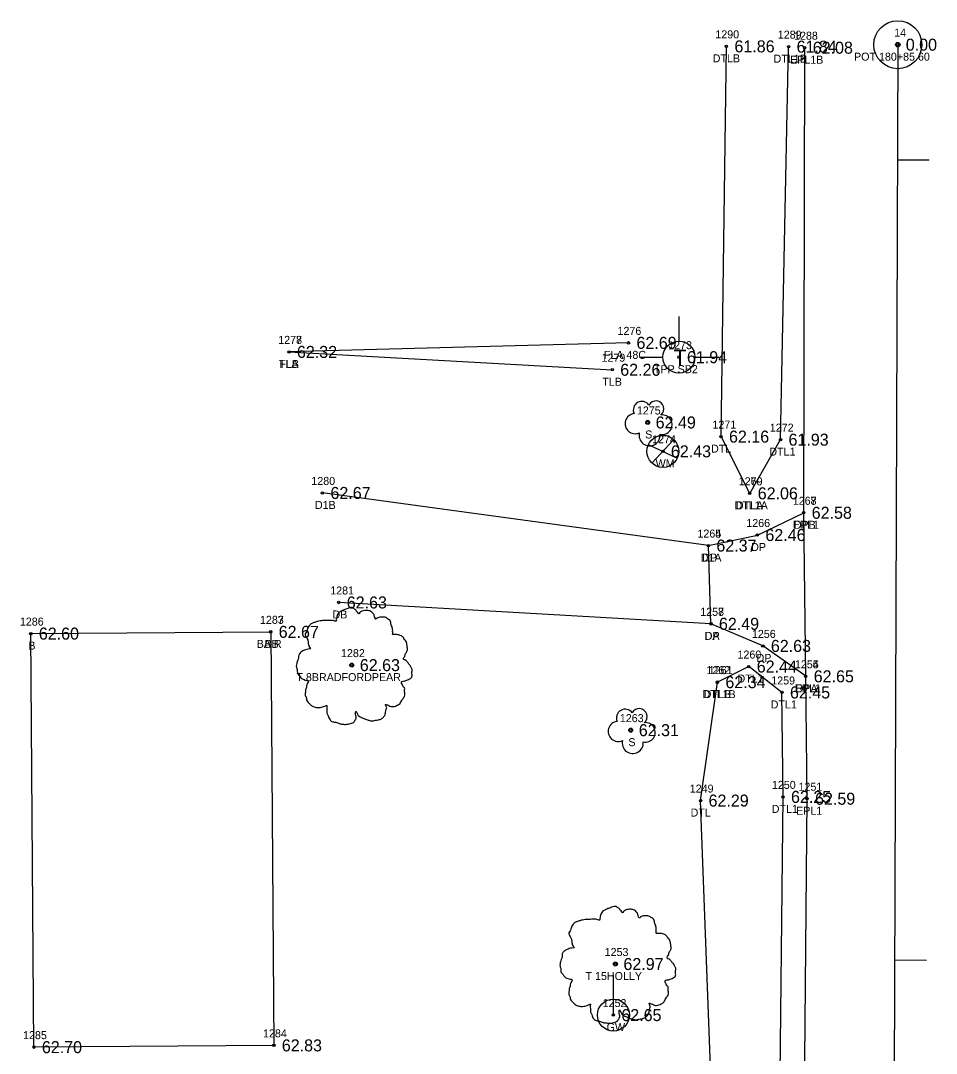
# Model space of a CAD drawing. Extents: x 2420113 to 2422887, y 845323 to 846653.
# Drawn here: x 2420851.4 to 2420965.9, y 846073.7 to 846202.8 of the extents above; entities that cross this region are included whole.
import ezdxf

# ---------------------------------------------------------------- set-up
doc = ezdxf.new("R2010")
doc.units = 0
for name, color, linetype in [('RD_EX_Bldg', 7, 'Continuous'), ('RD_EX_Bldg_txCode', 7, 'Continuous'), ('RD_EX_Driveway', 7, 'Continuous'), ('RD_EX_Driveway_txCode', 7, 'Continuous'), ('RD_EX_Fence_Other', 7, 'Continuous'), ('RD_EX_Fence_Other_txCode', 7, 'Continuous'), ('RD_EX_H2O', 7, 'Continuous'), ('RD_EX_H2O_txCode', 7, 'Continuous'), ('RD_EX_Road', 7, 'Continuous'), ('RD_EX_Road_txCode', 7, 'Continuous'), ('RD_EX_TX_Bldg_ELEV', 7, 'Continuous'), ('RD_EX_TX_Driveway_ELEV', 7, 'Continuous'), ('RD_EX_TX_Fence_Other_ELEV', 7, 'Continuous'), ('RD_EX_TX_H2O_ELEV', 7, 'Continuous'), ('RD_EX_TX_Road_ELEV', 7, 'Continuous'), ('RD_EX_TX_UT_ELEV', 7, 'Continuous'), ('RD_EX_TX_VEG_ELEV', 7, 'Continuous'), ('RD_EX_UT', 7, 'Continuous'), ('RD_EX_UT_txCode', 7, 'Continuous'), ('RD_EX_VEG', 7, 'Continuous'), ('RD_EX_VEG_txCode', 7, 'Continuous'), ('RD_HC_Cl', 7, 'Continuous'), ('RD_HC_Data', 7, 'Continuous'), ('RD_HC_Data_Tic', 7, 'Continuous'), ('RD_HC_Survey_ELEV', 7, 'Continuous'), ('RD_HC_txCode', 7, 'Continuous'), ('RD_SMD_Locator', 7, 'Continuous')]:
    doc.layers.add(name, color=color, linetype=linetype)

msp = doc.modelspace()

# ---------------------------------------------------------------- linework, layer by layer
at = {"layer": 'RD_EX_Bldg'}
msp.add_lwpolyline([(2420882.64, 846126.42), (2420883.03, 846074.73), (2420853.03, 846074.51), (2420852.65, 846126.2), (2420882.64, 846126.42)], dxfattribs=at)
at = {"layer": 'RD_EX_Driveway'}
for p, q in [((2420937.36, 846137.2), (2420889.11, 846143.78)), ((2420937.68, 846127.42), (2420891.15, 846130.09))]:
    msp.add_line(p, q, dxfattribs=at)
msp.add_lwpolyline([(2420949.53, 846120.86), (2420944.17, 846124.66), (2420937.68, 846127.42), (2420937.36, 846137.2), (2420943.49, 846138.52), (2420949.28, 846141.3)], dxfattribs=at)
at = {"layer": 'RD_EX_Fence_Other'}
msp.add_line((2420927.37, 846162.54), (2420884.92, 846161.41), dxfattribs=at)
at = {"layer": 'RD_EX_H2O'}
for points in [[(2420942.53, 846143.73), (2420938.94, 846150.82), (2420939.62, 846199.6)], [(2420942.53, 846143.73), (2420946.38, 846150.44), (2420947.39, 846199.56)], [(2420940.5, 845999.01), (2420945.76, 846017.04), (2420946.69, 846105.79), (2420946.56, 846118.84), (2420942.41, 846122.08), (2420938.49, 846120.13)], [(2420940.5, 845999.01), (2420939.71, 846016.55), (2420936.38, 846105.33), (2420938.49, 846120.13)]]:
    msp.add_lwpolyline(points, dxfattribs=at)
at = {"layer": 'RD_EX_Road'}
msp.add_lwpolyline([(2420911.08, 845716.87), (2420926.22, 845723.04), (2420936.01, 845731.06), (2420942.67, 845742.11), (2420946.54, 845756.04), (2420945.56, 845775.49), (2420946.2, 845794.55), (2420948.14, 845835.31), (2420948.56, 845856.76), (2420948.65, 845897.5), (2420947.59, 845964.03), (2420948.31, 845983.28), (2420948.75, 845998.25), (2420949.7, 846105.56), (2420949.53, 846120.86), (2420949.28, 846141.3), (2420949.41, 846199.43)], dxfattribs=at)
at = {"layer": 'RD_EX_UT'}
for p, q in [((2420933.68, 846165.82), (2420933.68, 846162.75)), ((2420928.75, 846160.76), (2420931.68, 846160.76)), ((2420935.68, 846160.76), (2420938.75, 846160.76)), ((2420930.31, 846147.52), (2420932.98, 846150.42)), ((2420929.83, 846149.82), (2420933.46, 846148.11)), ((2420925.48, 846078.52), (2420925.48, 846083.52))]:
    msp.add_line(p, q, dxfattribs=at)
for centre in [(2420933.68, 846160.75), (2420931.67, 846148.98), (2420925.48, 846078.52)]:
    msp.add_circle(centre, 2, dxfattribs=at)
at = {"layer": 'RD_EX_VEG'}
msp.add_line((2420884.92, 846161.41), (2420925.34, 846159.18), dxfattribs=at)
for centre, radius in [((2420929.77, 846152.59), 0.25), ((2420892.78, 846122.26), 0.25), ((2420892.77, 846122.24), 0.0001), ((2420927.66, 846114.13), 0.25), ((2420925.74, 846084.9), 0.25), ((2420925.73, 846084.88), 0.0001)]:
    msp.add_circle(centre, radius, dxfattribs=at)
for centre, radius, start, end in [((2420929.05, 846154.14), 1.08, 34.9763, 204.756), ((2420930.81, 846154.29), 0.995, 308.7626, 152.0467), ((2420928.2, 846152.44), 1.26, 96.4518, 294.734), ((2420931.61, 846152.31), 1.22, 256.5667, 98.1046), ((2420930.01, 846150.99), 1.32, 166.8827, 5.7589), ((2420926.94, 846115.67), 1.08, 34.9763, 204.756), ((2420928.7, 846115.83), 0.995, 308.7626, 152.0467), ((2420926.09, 846113.97), 1.26, 96.4518, 294.734), ((2420929.5, 846113.85), 1.22, 256.5667, 98.1046), ((2420927.9, 846112.53), 1.32, 166.8827, 5.7589)]:
    msp.add_arc(centre, radius, start, end, dxfattribs=at)
for points in [[(2420892.91, 846129.42), (2420892.61, 846129.45), (2420892.29, 846129.35), (2420892.04, 846129.25), (2420891.81, 846129.17), (2420891.59, 846129.07), (2420891.29, 846128.9), (2420891.06, 846128.7), (2420890.94, 846128.45), (2420890.89, 846128.22), (2420890.84, 846127.95), (2420890.84, 846127.78), (2420890.71, 846127.75), (2420890.56, 846127.78), (2420890.31, 846127.85), (2420890.06, 846127.85), (2420889.81, 846127.85), (2420889.46, 846127.83), (2420889.11, 846127.83), (2420888.84, 846127.78), (2420888.51, 846127.73), (2420888.14, 846127.6), (2420887.79, 846127.48), (2420887.49, 846127.23), (2420887.24, 846126.75), (2420887.11, 846126.4), (2420886.96, 846126.15), (2420887.11, 846125.7), (2420887.29, 846125.35), (2420887.31, 846125.15), (2420887.39, 846124.73), (2420887.49, 846124.5), (2420887.61, 846124.3), (2420887.54, 846124.28), (2420887.16, 846124.23), (2420886.86, 846124.13), (2420886.44, 846123.9), (2420886.22, 846123.68), (2420886.12, 846123.35), (2420886.09, 846123), (2420885.99, 846122.8), (2420885.92, 846122.53), (2420885.89, 846122.45), (2420885.84, 846122.13), (2420885.94, 846121.68), (2420885.97, 846121.33), (2420886.09, 846121.1), (2420886.24, 846120.93), (2420886.42, 846120.68), (2420886.81, 846120.45), (2420887.14, 846120.35), (2420887.34, 846120.33), (2420887.16, 846119.83), (2420887.11, 846119.48), (2420886.99, 846119.08), (2420886.99, 846119), (2420886.94, 846118.53), (2420887.09, 846118.2), (2420887.16, 846117.83), (2420887.34, 846117.6), (2420887.61, 846117.3), (2420887.94, 846117.08), (2420888.44, 846116.95), (2420888.84, 846116.98), (2420889.41, 846117.15), (2420889.66, 846117.23), (2420889.64, 846117.05), (2420889.66, 846116.68), (2420889.66, 846116.26), (2420889.81, 846115.93), (2420889.91, 846115.66), (2420890.06, 846115.41), (2420890.39, 846115.18), (2420890.79, 846115.11), (2420891.21, 846114.96), (2420891.66, 846114.88), (2420892.16, 846114.86), (2420892.76, 846115.01), (2420893.04, 846115.13), (2420893.14, 846115.31), (2420893.34, 846115.68), (2420893.29, 846115.91), (2420893.31, 846116.51), (2420893.41, 846116.33), (2420893.59, 846115.98), (2420894.09, 846115.68), (2420894.49, 846115.51), (2420894.96, 846115.36), (2420895.26, 846115.28), (2420895.74, 846115.36), (2420896.11, 846115.43), (2420896.49, 846115.56), (2420896.79, 846115.83), (2420896.96, 846116.11), (2420897.01, 846116.38), (2420897.09, 846116.75), (2420897.14, 846116.93)], [(2420897.14, 846116.93), (2420897.06, 846117.1), (2420897.01, 846117.35), (2420897.09, 846117.33), (2420897.26, 846117.28), (2420897.54, 846117.15), (2420897.76, 846117.08), (2420898.09, 846117.1), (2420898.36, 846117.2), (2420898.81, 846117.48), (2420899.08, 846117.95), (2420899.36, 846118.35), (2420899.43, 846118.68), (2420899.38, 846118.9), (2420899.36, 846119.4), (2420899.16, 846119.65), (2420899.11, 846119.78), (2420899.01, 846120.18), (2420899.08, 846120.23), (2420899.36, 846120.28), (2420899.73, 846120.4), (2420900.01, 846120.53), (2420900.23, 846120.7), (2420900.31, 846120.93), (2420900.28, 846121.33), (2420900.33, 846121.73), (2420900.26, 846121.88), (2420900.16, 846122.03), (2420900.08, 846122.23), (2420899.93, 846122.38), (2420899.83, 846122.53), (2420899.73, 846122.63), (2420899.61, 846122.78), (2420899.43, 846122.9), (2420899.28, 846122.95), (2420899.23, 846123.1), (2420899.38, 846123.3), (2420899.43, 846123.4), (2420899.46, 846123.63), (2420899.68, 846123.98), (2420899.73, 846124.38), (2420899.68, 846124.8), (2420899.63, 846125.08), (2420899.48, 846125.35), (2420899.28, 846125.6), (2420899.16, 846125.78), (2420898.98, 846125.9), (2420898.66, 846126.03), (2420898.41, 846126.08), (2420898.06, 846126.08), (2420897.86, 846126.13), (2420897.89, 846126.18), (2420897.89, 846126.33), (2420897.89, 846126.6), (2420897.81, 846127.05), (2420897.66, 846127.55), (2420897.66, 846127.58), (2420897.56, 846127.83), (2420897.34, 846128.02), (2420897.16, 846128.12), (2420896.96, 846128.25), (2420896.71, 846128.27), (2420896.41, 846128.27), (2420896.14, 846128.22), (2420895.94, 846128.12), (2420895.76, 846128), (2420895.69, 846128.15), (2420895.59, 846128.45), (2420895.54, 846128.6), (2420895.39, 846128.77), (2420895.16, 846128.97), (2420894.71, 846129.1), (2420894.09, 846129.02), (2420893.79, 846128.82), (2420893.64, 846128.65), (2420893.59, 846128.77), (2420893.39, 846128.97), (2420893.29, 846129.15), (2420893.11, 846129.27), (2420892.96, 846129.37), (2420892.86, 846129.42)], [(2420925.87, 846092.07), (2420925.57, 846092.09), (2420925.25, 846091.99), (2420925, 846091.89), (2420924.77, 846091.82), (2420924.55, 846091.72), (2420924.25, 846091.55), (2420924.02, 846091.35), (2420923.9, 846091.1), (2420923.85, 846090.87), (2420923.8, 846090.6), (2420923.8, 846090.42), (2420923.67, 846090.4), (2420923.52, 846090.42), (2420923.27, 846090.5), (2420923.02, 846090.5), (2420922.77, 846090.5), (2420922.42, 846090.47), (2420922.07, 846090.47), (2420921.8, 846090.42), (2420921.47, 846090.37), (2420921.1, 846090.25), (2420920.75, 846090.12), (2420920.45, 846089.87), (2420920.2, 846089.4), (2420920.07, 846089.05), (2420919.92, 846088.8), (2420920.07, 846088.35), (2420920.25, 846088), (2420920.27, 846087.8), (2420920.35, 846087.37), (2420920.45, 846087.15), (2420920.57, 846086.95), (2420920.5, 846086.92), (2420920.12, 846086.87), (2420919.82, 846086.77), (2420919.4, 846086.55), (2420919.17, 846086.32), (2420919.07, 846086), (2420919.05, 846085.65), (2420918.95, 846085.45), (2420918.87, 846085.17), (2420918.85, 846085.1), (2420918.8, 846084.77), (2420918.9, 846084.32), (2420918.92, 846083.97), (2420919.05, 846083.75), (2420919.2, 846083.57), (2420919.37, 846083.32), (2420919.77, 846083.1), (2420920.1, 846083), (2420920.3, 846082.97), (2420920.12, 846082.47), (2420920.07, 846082.12), (2420919.95, 846081.72), (2420919.95, 846081.65), (2420919.9, 846081.17), (2420920.05, 846080.85), (2420920.12, 846080.47), (2420920.3, 846080.25), (2420920.57, 846079.95), (2420920.9, 846079.73), (2420921.4, 846079.6), (2420921.8, 846079.63), (2420922.37, 846079.8), (2420922.62, 846079.88), (2420922.6, 846079.7), (2420922.62, 846079.33), (2420922.62, 846078.9), (2420922.77, 846078.58), (2420922.87, 846078.3), (2420923.02, 846078.05), (2420923.35, 846077.83), (2420923.75, 846077.75), (2420924.17, 846077.6), (2420924.62, 846077.53), (2420925.12, 846077.5), (2420925.72, 846077.65), (2420926, 846077.78), (2420926.1, 846077.95), (2420926.3, 846078.33), (2420926.25, 846078.55), (2420926.27, 846079.15), (2420926.37, 846078.98), (2420926.55, 846078.63), (2420927.05, 846078.33), (2420927.45, 846078.15), (2420927.92, 846078), (2420928.22, 846077.93), (2420928.69, 846078), (2420929.07, 846078.08), (2420929.44, 846078.2), (2420929.74, 846078.48), (2420929.92, 846078.75), (2420929.97, 846079.03), (2420930.04, 846079.4), (2420930.09, 846079.58)], [(2420930.09, 846079.58), (2420930.02, 846079.75), (2420929.97, 846080), (2420930.04, 846079.98), (2420930.22, 846079.93), (2420930.49, 846079.8), (2420930.72, 846079.73), (2420931.04, 846079.75), (2420931.32, 846079.85), (2420931.77, 846080.13), (2420932.04, 846080.6), (2420932.32, 846081), (2420932.39, 846081.32), (2420932.34, 846081.55), (2420932.32, 846082.05), (2420932.12, 846082.3), (2420932.07, 846082.42), (2420931.97, 846082.82), (2420932.04, 846082.87), (2420932.32, 846082.92), (2420932.69, 846083.05), (2420932.97, 846083.17), (2420933.19, 846083.35), (2420933.27, 846083.57), (2420933.24, 846083.97), (2420933.29, 846084.37), (2420933.22, 846084.52), (2420933.12, 846084.67), (2420933.04, 846084.87), (2420932.89, 846085.02), (2420932.79, 846085.17), (2420932.69, 846085.27), (2420932.57, 846085.42), (2420932.39, 846085.55), (2420932.24, 846085.6), (2420932.19, 846085.75), (2420932.34, 846085.95), (2420932.39, 846086.05), (2420932.42, 846086.27), (2420932.64, 846086.62), (2420932.69, 846087.02), (2420932.64, 846087.45), (2420932.59, 846087.72), (2420932.44, 846088), (2420932.24, 846088.25), (2420932.12, 846088.42), (2420931.94, 846088.55), (2420931.62, 846088.67), (2420931.37, 846088.72), (2420931.02, 846088.72), (2420930.82, 846088.77), (2420930.84, 846088.82), (2420930.84, 846088.97), (2420930.84, 846089.25), (2420930.77, 846089.7), (2420930.62, 846090.2), (2420930.62, 846090.22), (2420930.52, 846090.47), (2420930.29, 846090.67), (2420930.12, 846090.77), (2420929.92, 846090.9), (2420929.67, 846090.92), (2420929.37, 846090.92), (2420929.09, 846090.87), (2420928.89, 846090.77), (2420928.72, 846090.65), (2420928.64, 846090.8), (2420928.54, 846091.1), (2420928.49, 846091.25), (2420928.35, 846091.42), (2420928.12, 846091.62), (2420927.67, 846091.74), (2420927.05, 846091.67), (2420926.75, 846091.47), (2420926.6, 846091.3), (2420926.55, 846091.42), (2420926.35, 846091.62), (2420926.25, 846091.79), (2420926.07, 846091.92), (2420925.92, 846092.02), (2420925.82, 846092.07)]]:
    msp.add_spline(points, degree=3, dxfattribs=at)
at = {"layer": 'RD_HC_Cl'}
msp.add_line((2420961.04, 846199.81), (2420959.23, 845699.82), dxfattribs=at)
at = {"layer": 'RD_HC_Data'}
for radius in [3, 0.282]:
    msp.add_circle((2420961.04, 846199.81), radius, dxfattribs=at)
at = {"layer": 'RD_HC_Data_Tic'}
for p, q in [((2420960.98, 846185.41), (2420964.98, 846185.4)), ((2420960.62, 846085.41), (2420964.62, 846085.4))]:
    msp.add_line(p, q, dxfattribs=at)
at = {"layer": 'RD_SMD_Locator'}
for centre in [(2420939.62, 846199.6), (2420947.39, 846199.56), (2420949.41, 846199.43), (2420961.04, 846199.81), (2420927.37, 846162.54), (2420884.92, 846161.41), (2420884.92, 846161.41), (2420933.68, 846160.75), (2420925.34, 846159.18), (2420929.77, 846152.59), (2420938.94, 846150.82), (2420946.38, 846150.44), (2420931.67, 846148.98), (2420889.11, 846143.78), (2420942.53, 846143.73), (2420942.53, 846143.73), (2420949.28, 846141.3), (2420949.28, 846141.3), (2420943.49, 846138.52), (2420937.36, 846137.2), (2420937.36, 846137.2), (2420891.15, 846130.09), (2420937.68, 846127.42), (2420937.68, 846127.42), (2420852.65, 846126.2), (2420882.64, 846126.42), (2420882.64, 846126.42), (2420944.17, 846124.66), (2420892.78, 846122.26), (2420942.41, 846122.08), (2420949.53, 846120.86), (2420949.53, 846120.86), (2420938.49, 846120.13), (2420938.49, 846120.13), (2420946.56, 846118.84), (2420927.66, 846114.13), (2420936.38, 846105.33), (2420946.69, 846105.79), (2420949.7, 846105.56), (2420925.74, 846084.9), (2420925.48, 846078.52), (2420853.03, 846074.51), (2420883.03, 846074.73)]:
    msp.add_circle(centre, 0.15, dxfattribs=at)

# ---------------------------------------------------------------- texts
at = {"layer": 'RD_EX_Bldg_txCode'}
for s, p in [('1286', (2420851.28, 846127.2)), ('1283', (2420881.3, 846127.42)), ('1287', (2420881.3, 846127.42)), ('B', (2420852.34, 846124.2)), ('BA R', (2420880.89, 846124.42)), ('BB', (2420881.86, 846124.42)), ('1285', (2420851.68, 846075.51)), ('1284', (2420881.68, 846075.73))]:
    msp.add_text(s, height=1, dxfattribs=at).set_placement(p)
at = {"layer": 'RD_EX_Driveway_txCode'}
for s, p in [('1280', (2420887.72, 846144.78)), ('D1B', (2420888.17, 846141.78)), ('1267', (2420947.91, 846142.3)), ('1266', (2420942.1, 846139.52)), ('DPB', (2420948.03, 846139.3)), ('1264', (2420935.99, 846138.2)), ('1265', (2420935.99, 846138.2)), ('DP', (2420942.71, 846136.52)), ('D1A', (2420936.4, 846135.2)), ('DP', (2420936.58, 846135.2)), ('1281', (2420890.08, 846131.09)), ('DB', (2420890.37, 846128.09)), ('1257', (2420936.34, 846128.42)), ('1258', (2420936.34, 846128.42)), ('DA', (2420936.89, 846125.42)), ('DP', (2420936.91, 846125.42)), ('1256', (2420942.8, 846125.66)), ('DP', (2420943.39, 846122.66)), ('1255', (2420948.18, 846121.86)), ('DPA', (2420948.26, 846118.86))]:
    msp.add_text(s, height=1, dxfattribs=at).set_placement(p)
at = {"layer": 'RD_EX_Fence_Other_txCode'}
for s, p in [('1277', (2420883.58, 846162.41)), ('1276', (2420926, 846163.54)), ('FLA 48C', (2420924.29, 846160.54)), ('FLB', (2420883.72, 846159.41))]:
    msp.add_text(s, height=1, dxfattribs=at).set_placement(p)
at = {"layer": 'RD_EX_H2O_txCode'}
for s, p in [('1290', (2420938.23, 846200.6)), ('1289', (2420946.04, 846200.56)), ('DTLB', (2420937.9, 846197.6)), ('DTL1B', (2420945.51, 846197.56)), ('1271', (2420937.87, 846151.82)), ('1272', (2420945.04, 846151.44)), ('DTL', (2420937.69, 846148.82)), ('DTL1', (2420944.98, 846148.44)), ('1270', (2420941.15, 846144.73)), ('1269', (2420941.16, 846144.73)), ('DTL1A', (2420940.63, 846141.73)), ('DTLA', (2420940.8, 846141.73)), ('1260', (2420941, 846123.08)), ('1262', (2420937.12, 846121.13)), ('1261', (2420937.4, 846121.13)), ('DTL1', (2420941, 846120.08)), ('1259', (2420945.22, 846119.84)), ('DTL1B', (2420936.61, 846118.13)), ('DTLB', (2420936.77, 846118.13)), ('DTL1', (2420945.15, 846116.84)), ('1249', (2420935.03, 846106.33)), ('1250', (2420945.3, 846106.79)), ('DTL', (2420935.14, 846103.33)), ('DTL1', (2420945.28, 846103.79))]:
    msp.add_text(s, height=1, dxfattribs=at).set_placement(p)
at = {"layer": 'RD_EX_Road_txCode'}
for s, p in [('1288', (2420948.07, 846200.43)), ('EPL1B', (2420947.57, 846197.43)), ('1268', (2420947.91, 846142.3)), ('EPL1', (2420947.91, 846139.3)), ('1254', (2420948.18, 846121.86)), ('EPL1', (2420948.16, 846118.86)), ('1251', (2420948.63, 846106.56)), ('EPL1', (2420948.33, 846103.56))]:
    msp.add_text(s, height=1, dxfattribs=at).set_placement(p)
at = {"layer": 'RD_EX_TX_Bldg_ELEV'}
for s, p in [('62.67', (2420883.64, 846125.67)), ('62.67', (2420883.64, 846125.67)), ('62.60', (2420853.65, 846125.45)), ('62.70', (2420854.03, 846073.76)), ('62.83', (2420884.03, 846073.98))]:
    msp.add_text(s, height=1.5, dxfattribs=at).set_placement(p)
at = {"layer": 'RD_EX_TX_Driveway_ELEV'}
for s, p in [('62.67', (2420890.11, 846143.03)), ('62.58', (2420950.28, 846140.55)), ('62.46', (2420944.49, 846137.77)), ('62.37', (2420938.36, 846136.45)), ('62.37', (2420938.36, 846136.45)), ('62.63', (2420892.15, 846129.34)), ('62.49', (2420938.68, 846126.67)), ('62.49', (2420938.68, 846126.67)), ('62.63', (2420945.17, 846123.91)), ('62.65', (2420950.53, 846120.11))]:
    msp.add_text(s, height=1.5, dxfattribs=at).set_placement(p)
at = {"layer": 'RD_EX_TX_Fence_Other_ELEV'}
for s, p in [('62.69', (2420928.37, 846161.79)), ('62.32', (2420885.92, 846160.66))]:
    msp.add_text(s, height=1.5, dxfattribs=at).set_placement(p)
at = {"layer": 'RD_EX_TX_H2O_ELEV'}
for s, p in [('61.86', (2420940.62, 846198.85)), ('61.84', (2420948.39, 846198.81)), ('62.16', (2420939.94, 846150.07)), ('61.93', (2420947.38, 846149.69)), ('62.06', (2420943.53, 846142.98)), ('62.06', (2420943.53, 846142.98)), ('62.44', (2420943.41, 846121.33)), ('62.34', (2420939.49, 846119.38)), ('62.34', (2420939.49, 846119.38)), ('62.45', (2420947.56, 846118.09)), ('62.25', (2420947.69, 846105.04)), ('62.29', (2420937.38, 846104.58))]:
    msp.add_text(s, height=1.5, dxfattribs=at).set_placement(p)
at = {"layer": 'RD_EX_TX_Road_ELEV'}
for s, p in [('62.08', (2420950.41, 846198.68)), ('62.58', (2420950.28, 846140.55)), ('62.65', (2420950.53, 846120.11)), ('62.59', (2420950.7, 846104.81))]:
    msp.add_text(s, height=1.5, dxfattribs=at).set_placement(p)
at = {"layer": 'RD_EX_TX_UT_ELEV'}
for s, p in [('61.94', (2420934.68, 846160)), ('62.43', (2420932.67, 846148.23)), ('62.65', (2420926.48, 846077.77))]:
    msp.add_text(s, height=1.5, dxfattribs=at).set_placement(p)
at = {"layer": 'RD_EX_TX_VEG_ELEV'}
for s, p in [('62.32', (2420885.92, 846160.66)), ('62.26', (2420926.34, 846158.43)), ('62.49', (2420930.77, 846151.84)), ('62.63', (2420893.78, 846121.51)), ('62.31', (2420928.66, 846113.38)), ('62.97', (2420926.74, 846084.15))]:
    msp.add_text(s, height=1.5, dxfattribs=at).set_placement(p)
at = {"layer": 'RD_EX_UT'}
msp.add_text('T', height=2, dxfattribs=at).set_placement((2420933.01, 846159.7))
at = {"layer": 'RD_EX_UT_txCode'}
for s, p in [('1273', (2420932.33, 846161.75)), ('TPP SB2', (2420930.54, 846158.75)), ('1274', (2420930.32, 846149.98)), ('WM', (2420930.76, 846146.98)), ('1252', (2420924.14, 846079.52)), ('GW', (2420924.64, 846076.52))]:
    msp.add_text(s, height=1, dxfattribs=at).set_placement(p)
at = {"layer": 'RD_EX_VEG_txCode'}
for s, p in [('1278', (2420883.58, 846162.41)), ('1279', (2420924, 846160.18)), ('TLA', (2420883.66, 846159.41)), ('TLB', (2420924.1, 846157.18)), ('1275', (2420928.42, 846153.59)), ('S', (2420929.46, 846150.59)), ('1282', (2420891.43, 846123.26)), ('T 8BRADFORDPEAR', (2420885.85, 846120.26)), ('1263', (2420926.29, 846115.13)), ('S', (2420927.35, 846112.13)), ('1253', (2420924.39, 846085.9)), ('T 15HOLLY', (2420922, 846082.9))]:
    msp.add_text(s, height=1, dxfattribs=at).set_placement(p)
at = {"layer": 'RD_HC_Survey_ELEV'}
msp.add_text('0.00', height=1.5, dxfattribs=at).set_placement((2420962.04, 846199.06))
at = {"layer": 'RD_HC_txCode'}
for s, p in [('14', (2420960.59, 846200.81)), ('POT 180+85.60', (2420955.57, 846197.81))]:
    msp.add_text(s, height=1, dxfattribs=at).set_placement(p)

doc.saveas('drawing.dxf')
